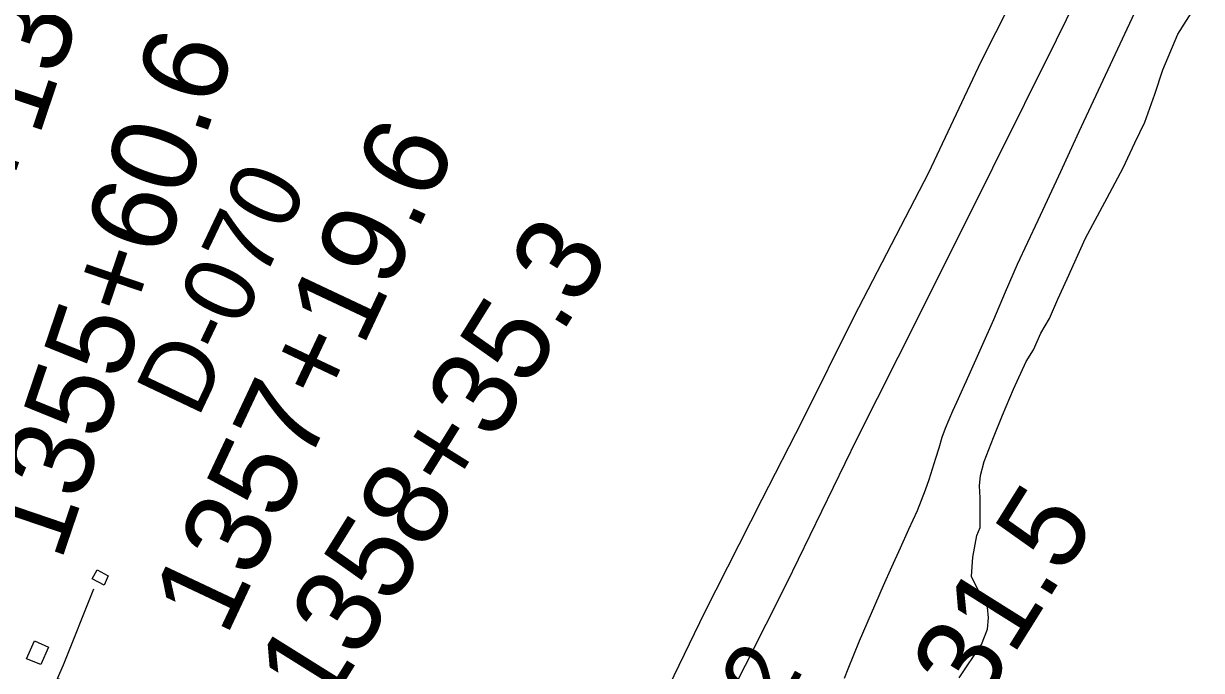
# Model space of a CAD drawing. Extents: x 3734862 to 3772949, y 391520 to 417239.
# Drawn here: x 3739114 to 3740497, y 409644 to 410402 of the extents above; entities that cross this region are included whole.
import ezdxf

# ---------------------------------------------------------------- set-up
doc = ezdxf.new("R2010")
doc.units = 0
for name, color, linetype in [('V-BLDG-OTLN', 7, 'Continuous'), ('V-RIVR-RANG-IDEN', 7, 'Continuous'), ('V-ROAD-CNTR', 7, 'Continuous'), ('V-SITE-VEGE', 7, 'Continuous'), ('V-SURV-IDEN', 7, 'Continuous'), ('V-TOPO-SHOR', 7, 'Continuous'), ('V-UTIL-LINE', 7, 'Continuous')]:
    doc.layers.add(name, color=color, linetype=linetype)

msp = doc.modelspace()

# ---------------------------------------------------------------- linework, layer by layer
at = {"layer": 'V-BLDG-OTLN'}
for points in [[(3739208.9, 409743.7), (3739195, 409751.1), (3739200.6, 409761.5), (3739213.7, 409754.5)], [(3739134.6, 409650.6), (3739117.7, 409657.3), (3739127, 409678.4), (3739143.6, 409671)]]:
    msp.add_lwpolyline(points, close=True, dxfattribs=at)
at = {"layer": 'V-ROAD-CNTR'}
for points in [[(3740192.3, 409917.3), (3740196.4, 409927.7), (3740200.6, 409938), (3740205, 409948.2), (3740209.6, 409958.4), (3740224.2, 409990.5), (3740238.6, 410022.8), (3740252.9, 410055.1), (3740266.9, 410087.5), (3740280.8, 410119.9), (3740305.1, 410171.8), (3740329.2, 410223.7), (3740353.1, 410275.8), (3740429.7, 410438.9)], [(3740077.9, 409634.4), (3740082.1, 409645.6), (3740095.6, 409678.3), (3740109.4, 409710.8), (3740123.5, 409743.3), (3740133.4, 409765.3), (3740143.4, 409787.3), (3740153.4, 409809.3), (3740163.5, 409831.2), (3740168.2, 409843.3), (3740172.7, 409855.5), (3740177, 409867.7), (3740181.1, 409880), (3740185.1, 409892.4), (3740188.8, 409904.8), (3740192.3, 409917.3)]]:
    msp.add_lwpolyline(points, dxfattribs=at)
at = {"layer": 'V-SITE-VEGE'}
for points in [[(3740263.1, 409943.2), (3740276.1, 409973.6), (3740291.2, 410005.9), (3740299.6, 410019.7), (3740308.2, 410039.2), (3740318.3, 410056.2), (3740328.3, 410078.9), (3740339.3, 410103), (3740360.8, 410150.6), (3740386.3, 410197.7), (3740404.9, 410233), (3740418.7, 410262.3), (3740430.5, 410286.5), (3740442.2, 410319.4), (3740451.3, 410347.8), (3740469, 410389.8), (3740492.1, 410426.1)], [(3740212.5, 409635), (3740238.6, 409673.9), (3740245.7, 409691.9), (3740246.7, 409705.5), (3740245.5, 409717.8), (3740235.1, 409736.9), (3740226.9, 409753.9), (3740228.4, 409776.5), (3740233.2, 409802), (3740236.9, 409811.2), (3740237, 409845.9), (3740236.1, 409860.1), (3740237.3, 409872.1), (3740241.7, 409888.8), (3740252.7, 409916.8), (3740263.1, 409943.2)]]:
    msp.add_lwpolyline(points, dxfattribs=at)
at = {"layer": 'V-TOPO-SHOR'}
for points in [[(3739867.4, 409484.5), (3739842.4, 409492.2), (3739825.6, 409498.1), (3739819.6, 409499.8), (3739812.8, 409504.5), (3739811.8, 409506.1), (3739811.3, 409511), (3739817.4, 409524.7), (3739859.8, 409600.7), (3739913.9, 409711.8), (3739981, 409844.5), (3740028.5, 409936.8), (3740089.3, 410058.6), (3740176.9, 410227.5), (3740238.3, 410357.8), (3740324.8, 410528.8)], [(3740397.5, 410527.9), (3740326.4, 410382.6), (3740251.6, 410232.5), (3740164.8, 410058.6), (3740092, 409914.3), (3740009.8, 409745.7), (3739936.9, 409601.4), (3739883.1, 409489.5), (3739879.7, 409484.6), (3739875.6, 409482.9), (3739872.3, 409482.2)]]:
    msp.add_lwpolyline(points, dxfattribs=at)
at = {"layer": 'V-UTIL-LINE'}
msp.add_lwpolyline([(3739059.9, 409463.9), (3739086.6, 409502.6), (3739106.8, 409541.8), (3739116, 409537.2), (3739120.2, 409543.3), (3739162.6, 409630.4), (3739154.1, 409634.3), (3739161.1, 409650.1), (3739196.9, 409739.5)], dxfattribs=at)

# ---------------------------------------------------------------- texts
at = {"layer": 'V-RIVR-RANG-IDEN'}
for s, rotation, p in [('D-070', 64.5793, (3739318.8, 409938)), ('R-55.2', 61.2037, (3739869.8, 409351.9))]:
    msp.add_text(s, height=83, rotation=rotation, dxfattribs=at).set_placement(p)
at = {"layer": 'V-SURV-IDEN'}
for s, rotation, p in [('1354+13.1', 71.3758, (3739012.2, 409912.1)), ('1355+60.6', 71.2033, (3739158, 409769.9)), ('1357+19.6', 64.7782, (3739352.1, 409681.9)), ('1358+35.3', 58.0048, (3739467.3, 409592)), ('1365+31.5', 57.9214, (3740036.2, 409278.2)), ('1369+23.4', 56.9106, (3740341, 409155.2))]:
    msp.add_text(s, height=100, rotation=rotation, dxfattribs=at).set_placement(p)

doc.saveas('drawing.dxf')
